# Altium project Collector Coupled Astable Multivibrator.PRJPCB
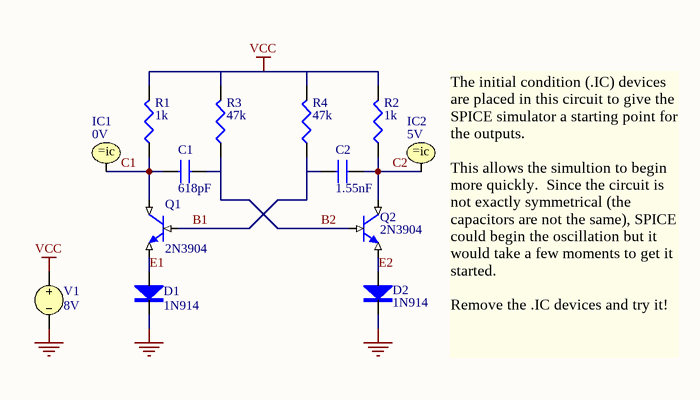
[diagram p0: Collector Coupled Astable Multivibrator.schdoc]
1 sheet, 13 parts. Net scope: global (net labels, ports and power ports of the same name join across sheets).

## Sheet Collector Coupled Astable Multivibrator.schdoc: Collector Coupled Astable Multivibrator
size A4; Organization: Altium Limited; Address1: L3, 12a Rodborough Rd; Address2: Frenchs Forest; Address3: NSW; Address4: Australia 2086; DocumentNumber: 1; SheetNumber: 1; SheetTotal: 1

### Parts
C1  618pF
C2  1.55nF
D1  1N914
D2  1N914
IC1  0V
IC2  5V
Q1  2N3904
Q2  2N3904
R1  1k
R2  1k
R3  47k
R4  47k
V1  value 8V  (hidden comment: VSRC)

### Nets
GND: D1.2(K) D2.2(K) V1.2
VCC: R1.1(TOP) R2.1(TOP) R3.1(TOP) R4.1(TOP) V1.1
B1: C2.1 Q1.2(B) R4.2(BOT)
B2: C1.2 Q2.2(B) R3.2(BOT)
C1: C1.1 IC1.1 Q1.1(C) R1.2(BOT)
C2: C2.2 IC2.1 Q2.1(C) R2.2(BOT)
E1: D1.1(A) Q1.3(E)
E2: D2.1(A) Q2.3(E)

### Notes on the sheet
- (near IC2) The initial condition (.IC) devices are placed in this circuit to give the SPICE simulator a starting point for the outputs.
  This allows the simultion to begin more quickly.  Since the circuit is not exactly symmetrical (the capacitors are not the same), SPICE could begin the oscillation but it would take a few moments to get it started.
  Remove the .IC devices and try it!

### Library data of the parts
C1 C2 = CAP: Capacitor
D1 D2 = 1N914: Diode
IC1 IC2 = .IC: Initial Condition
Q1 Q2 = 2N3904: NPN BJT
R1-R4 = RES: Resistor
V1 = VSRC: Voltage Source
